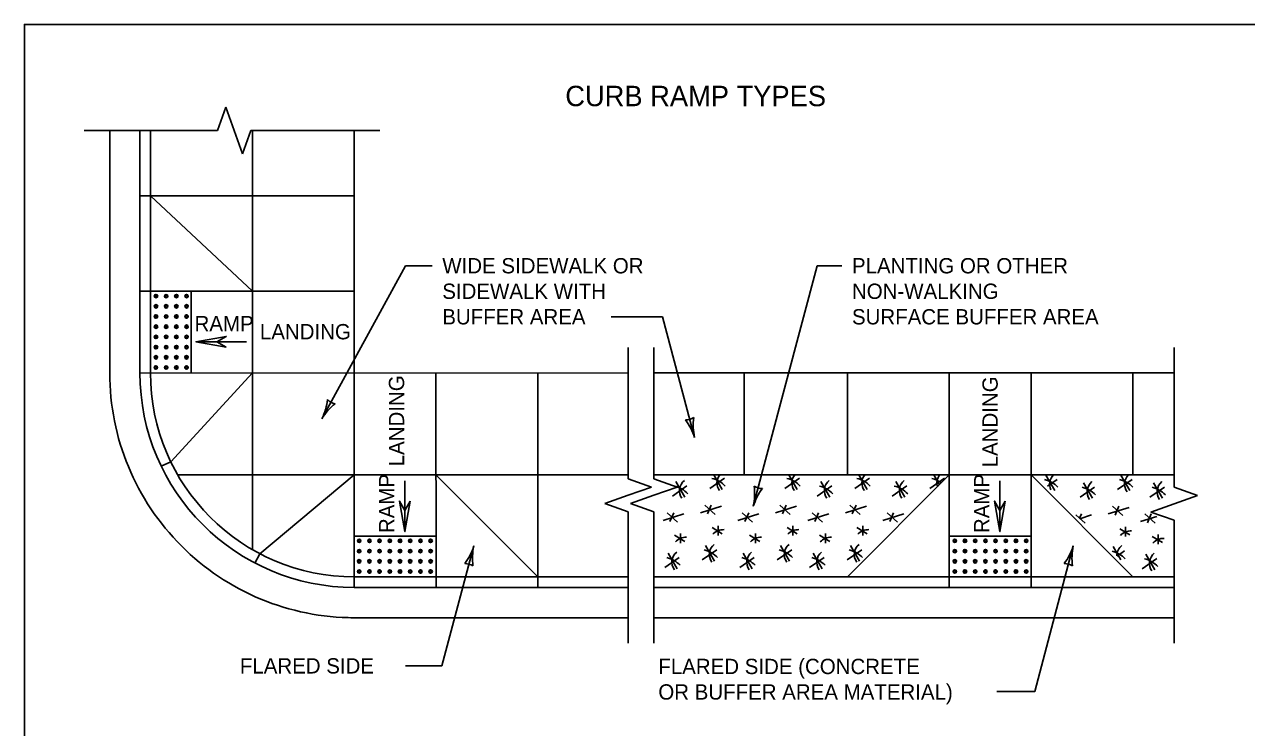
# Model space of a CAD drawing. Extents: x 49991.4 to 50021, y 49987.6 to 50011.4.
# Drawn here: x 50009.737 to 50014.53, y 50005.41 to 50008.165 of the extents above; entities that cross this region are included whole.
import ezdxf

# ---------------------------------------------------------------- set-up
doc = ezdxf.new("R2010")
doc.units = 0
for name, color, linetype in [('Level 1', 7, 'Continuous'), ('Level 2', 7, 'Continuous'), ('Level 3', 7, 'Continuous'), ('Level 6', 7, 'Continuous')]:
    doc.layers.add(name, color=color, linetype=linetype)

msp = doc.modelspace()

# ---------------------------------------------------------------- linework, layer by layer
at = {"layer": 'Level 1'}
for p, q in [((50010.072, 50006.7991), (50010.072, 50007.7489)), ((50010.1902, 50007.7489), (50010.1902, 50006.7991)), ((50010.2316, 50006.7991), (50010.2316, 50007.7489)), ((50010.6315, 50007.749), (50010.6315, 50006.1068)), ((50011.0308, 50007.749), (50011.0308, 50005.9583)), ((50011.0304, 50007.4931), (50010.1902, 50007.493)), ((50010.2314, 50007.493), (50010.6315, 50007.1196)), ((50011.0308, 50007.1196), (50010.1902, 50007.1195)), ((50010.3916, 50006.799), (50010.3917, 50007.1195)), ((50012.1053, 50006.7984), (50010.1902, 50006.7991)), ((50010.3113, 50006.4512), (50010.6315, 50006.799)), ((50011.3512, 50006.7988), (50011.3513, 50005.9583)), ((50011.7505, 50006.7989), (50011.7504, 50005.9584)), ((50012.2049, 50006.799), (50014.2452, 50006.7989)), ((50012.5597, 50006.7987), (50012.5598, 50006.3996)), ((50012.9648, 50006.7989), (50012.9647, 50006.3996)), ((50013.3641, 50006.799), (50013.3641, 50005.9585)), ((50013.6845, 50006.799), (50013.6846, 50005.9585)), ((50014.0838, 50006.7991), (50014.0838, 50006.3995)), ((50010.274, 50006.4332), (50010.3113, 50006.4512)), ((50012.1053, 50006.3995), (50010.3387, 50006.3995)), ((50010.6605, 50006.0909), (50011.0309, 50006.3997)), ((50011.3512, 50006.3996), (50011.7504, 50005.9998)), ((50012.2049, 50006.3996), (50014.2452, 50006.3995)), ((50012.205, 50006.3844), (50012.208, 50006.3865)), ((50012.2915, 50006.3732), (50012.3267, 50006.3122)), ((50012.4252, 50006.3469), (50012.4823, 50006.3865)), ((50012.4407, 50006.3996), (50012.4739, 50006.3422)), ((50012.7192, 50006.3469), (50012.7763, 50006.3865)), ((50012.7347, 50006.3996), (50012.7679, 50006.3422)), ((50012.8598, 50006.3732), (50012.895, 50006.3122)), ((50012.9645, 50005.9997), (50013.3641, 50006.3996)), ((50012.9935, 50006.3469), (50013.0506, 50006.3865)), ((50013.009, 50006.3996), (50013.0422, 50006.3422)), ((50013.1538, 50006.3732), (50013.189, 50006.3122)), ((50013.2875, 50006.3469), (50013.3446, 50006.3865)), ((50013.303, 50006.3996), (50013.3254, 50006.3609)), ((50013.6845, 50006.3997), (50014.0837, 50005.9997)), ((50013.743, 50006.3989), (50013.7783, 50006.3379)), ((50013.7485, 50006.3556), (50013.7867, 50006.3821)), ((50013.8899, 50006.3689), (50013.9251, 50006.3079)), ((50014.0236, 50006.3425), (50014.0807, 50006.3821)), ((50014.037, 50006.3989), (50014.0723, 50006.3379)), ((50014.1642, 50006.3689), (50014.1995, 50006.3079)), ((50012.2781, 50006.3169), (50012.3351, 50006.3565)), ((50012.8464, 50006.3169), (50012.9035, 50006.3565)), ((50013.1404, 50006.3169), (50013.1975, 50006.3565)), ((50013.8765, 50006.3125), (50013.9336, 50006.3521)), ((50014.1508, 50006.3125), (50014.2079, 50006.3521)), ((50012.1315, 50006.2808), (50012.1309, 50006.2814)), ((50012.3885, 50006.2509), (50012.4707, 50006.2769)), ((50012.4456, 50006.2448), (50012.4053, 50006.2814)), ((50012.4154, 50006.2464), (50012.4305, 50006.2814)), ((50012.6825, 50006.2509), (50012.7647, 50006.2769)), ((50012.7396, 50006.2448), (50012.6993, 50006.2814)), ((50012.7094, 50006.2464), (50012.7245, 50006.2814)), ((50012.9569, 50006.2509), (50013.039, 50006.2769)), ((50013.0139, 50006.2448), (50012.9736, 50006.2814)), ((50012.9837, 50006.2464), (50012.9988, 50006.2814)), ((50013.987, 50006.2465), (50014.0691, 50006.2725)), ((50014.044, 50006.2405), (50014.0037, 50006.277)), ((50014.0138, 50006.242), (50014.0289, 50006.277)), ((50012.2414, 50006.2209), (50012.3236, 50006.2469)), ((50012.2985, 50006.2148), (50012.2581, 50006.2514)), ((50012.2683, 50006.2164), (50012.2834, 50006.2514)), ((50012.5354, 50006.2209), (50012.6176, 50006.2469)), ((50012.5925, 50006.2148), (50012.5521, 50006.2514)), ((50012.5623, 50006.2164), (50012.5774, 50006.2514)), ((50012.8097, 50006.2209), (50012.8919, 50006.2469)), ((50012.8668, 50006.2148), (50012.8264, 50006.2514)), ((50012.8366, 50006.2164), (50012.8517, 50006.2514)), ((50013.1037, 50006.2209), (50013.1859, 50006.2469)), ((50013.1608, 50006.2148), (50013.1204, 50006.2514)), ((50013.1306, 50006.2164), (50013.1457, 50006.2514)), ((50013.8969, 50006.2105), (50013.8603, 50006.2436)), ((50013.8743, 50006.2296), (50013.8818, 50006.247)), ((50013.8759, 50006.228), (50013.922, 50006.2425)), ((50014.1142, 50006.2165), (50014.1773, 50006.2365)), ((50014.1712, 50006.2105), (50014.1309, 50006.247)), ((50014.141, 50006.212), (50014.1561, 50006.247)), ((50012.4336, 50006.1929), (50012.4739, 50006.1685)), ((50012.457, 50006.1625), (50012.457, 50006.2006)), ((50012.7276, 50006.1929), (50012.7679, 50006.1685)), ((50012.751, 50006.1625), (50012.751, 50006.2006)), ((50013.002, 50006.1929), (50013.0422, 50006.1685)), ((50013.0254, 50006.1625), (50013.0254, 50006.2006)), ((50014.0321, 50006.1886), (50014.0723, 50006.1642)), ((50014.0555, 50006.1581), (50014.0555, 50006.1962)), ((50011.3513, 50006.1597), (50011.0308, 50006.1597)), ((50012.2865, 50006.1629), (50012.3267, 50006.1385)), ((50012.3099, 50006.1325), (50012.3099, 50006.1706)), ((50012.5805, 50006.1629), (50012.6207, 50006.1385)), ((50012.6039, 50006.1325), (50012.6039, 50006.1706)), ((50012.8548, 50006.1629), (50012.895, 50006.1385)), ((50012.8782, 50006.1325), (50012.8782, 50006.1706)), ((50013.6846, 50006.1597), (50013.3641, 50006.1597)), ((50014.1592, 50006.1586), (50014.1995, 50006.1342)), ((50014.1826, 50006.1281), (50014.1826, 50006.1662)), ((50010.6413, 50006.0542), (50010.6605, 50006.0909)), ((50012.2615, 50006.0927), (50012.2967, 50006.0318)), ((50012.3952, 50006.0664), (50012.4523, 50006.106)), ((50012.4086, 50006.1227), (50012.4439, 50006.0618)), ((50012.5555, 50006.0927), (50012.5907, 50006.0318)), ((50012.6892, 50006.0664), (50012.7463, 50006.106)), ((50012.7026, 50006.1227), (50012.7379, 50006.0618)), ((50012.8298, 50006.0927), (50012.865, 50006.0318)), ((50012.9635, 50006.0664), (50013.0206, 50006.106)), ((50012.9769, 50006.1227), (50013.0122, 50006.0618)), ((50014.007, 50006.1184), (50014.037, 50006.0666)), ((50014.0219, 50006.0817), (50014.0507, 50006.1016)), ((50014.1342, 50006.0884), (50014.1695, 50006.0274)), ((50012.2481, 50006.0364), (50012.3051, 50006.076)), ((50012.5421, 50006.0364), (50012.5991, 50006.076)), ((50012.8164, 50006.0364), (50012.8735, 50006.076)), ((50014.1208, 50006.032), (50014.1779, 50006.0716)), ((50012.1052, 50005.9997), (50011.0308, 50005.9997)), ((50014.2452, 50005.9997), (50012.205, 50005.9997)), ((50011.0308, 50005.9583), (50012.1052, 50005.9583)), ((50012.205, 50005.9583), (50014.2452, 50005.9583)), ((50011.017, 50005.8401), (50012.1052, 50005.8401)), ((50012.205, 50005.8401), (50014.2452, 50005.84))]:
    msp.add_line(p, q, dxfattribs=at)
msp.add_lwpolyline([(50020.9378, 50008.1646), (50009.7374, 50008.1646), (50009.7374, 49999.8856), (50020.9378, 49999.8856)], close=True, dxfattribs=at)
msp.add_lwpolyline([(50020.9378, 50008.1646), (50009.7374, 50008.1646), (50009.7374, 49999.8856), (50020.9378, 49999.8856)], close=True, dxfattribs=at)
for centre, radius in [((50010.2531, 50007.1003), 0.00675), ((50010.2531, 50007.1003), 0.00375), ((50010.2931, 50007.1003), 0.00675), ((50010.2931, 50007.1003), 0.00375), ((50010.3331, 50007.1003), 0.00675), ((50010.3331, 50007.1003), 0.00375), ((50010.3731, 50007.1003), 0.00675), ((50010.3731, 50007.1003), 0.00375), ((50010.2531, 50007.0603), 0.00675), ((50010.2531, 50007.0603), 0.00375), ((50010.2931, 50007.0603), 0.00675), ((50010.2931, 50007.0603), 0.00375), ((50010.3331, 50007.0603), 0.00675), ((50010.3331, 50007.0603), 0.00375), ((50010.3731, 50007.0603), 0.00675), ((50010.3731, 50007.0603), 0.00375), ((50010.2531, 50007.0203), 0.00675), ((50010.2531, 50007.0203), 0.00375), ((50010.2931, 50007.0203), 0.00675), ((50010.2931, 50007.0203), 0.00375), ((50010.3331, 50007.0203), 0.00675), ((50010.3331, 50007.0203), 0.00375), ((50010.3731, 50007.0203), 0.00675), ((50010.3731, 50007.0203), 0.00375), ((50010.2531, 50006.9803), 0.00675), ((50010.2531, 50006.9403), 0.00675), ((50010.2531, 50006.9803), 0.00375), ((50010.2531, 50006.9403), 0.00375), ((50010.2931, 50006.9803), 0.00675), ((50010.2931, 50006.9403), 0.00675), ((50010.2931, 50006.9803), 0.00375), ((50010.2931, 50006.9403), 0.00375), ((50010.3331, 50006.9803), 0.00675), ((50010.3331, 50006.9403), 0.00675), ((50010.3331, 50006.9803), 0.00375), ((50010.3331, 50006.9403), 0.00375), ((50010.3731, 50006.9803), 0.00675), ((50010.3731, 50006.9403), 0.00675), ((50010.3731, 50006.9803), 0.00375), ((50010.3731, 50006.9403), 0.00375), ((50010.2531, 50006.9003), 0.00675), ((50010.2531, 50006.9003), 0.00375), ((50010.2931, 50006.9003), 0.00675), ((50010.2931, 50006.9003), 0.00375), ((50010.3331, 50006.9003), 0.00675), ((50010.3331, 50006.9003), 0.00375), ((50010.3731, 50006.9003), 0.00675), ((50010.3731, 50006.9003), 0.00375), ((50010.253, 50006.8603), 0.00675), ((50010.253, 50006.8603), 0.00375), ((50010.293, 50006.8603), 0.00675), ((50010.293, 50006.8603), 0.00375), ((50010.333, 50006.8603), 0.00675), ((50010.333, 50006.8603), 0.00375), ((50010.373, 50006.8603), 0.00675), ((50010.373, 50006.8603), 0.00375), ((50010.253, 50006.8203), 0.00675), ((50010.253, 50006.8203), 0.00375), ((50010.293, 50006.8203), 0.00675), ((50010.293, 50006.8203), 0.00375), ((50010.333, 50006.8203), 0.00675), ((50010.333, 50006.8203), 0.00375), ((50010.373, 50006.8203), 0.00675), ((50010.373, 50006.8203), 0.00375), ((50011.0501, 50006.1411), 0.00675), ((50011.0501, 50006.1411), 0.00375), ((50011.0901, 50006.1411), 0.00675), ((50011.0901, 50006.1411), 0.00375), ((50011.1301, 50006.1411), 0.00675), ((50011.1301, 50006.1411), 0.00375), ((50011.1701, 50006.1411), 0.00675), ((50011.1701, 50006.1411), 0.00375), ((50011.2101, 50006.1411), 0.00675), ((50011.2101, 50006.1411), 0.00375), ((50011.2501, 50006.1411), 0.00675), ((50011.2501, 50006.1411), 0.00375), ((50011.2901, 50006.1411), 0.00675), ((50011.2901, 50006.1411), 0.00375), ((50011.3301, 50006.1411), 0.00675), ((50011.3301, 50006.1411), 0.00375), ((50013.3855, 50006.1411), 0.00675), ((50013.3855, 50006.1411), 0.00375), ((50013.4255, 50006.1411), 0.00675), ((50013.4255, 50006.1411), 0.00375), ((50013.4655, 50006.1411), 0.00675), ((50013.4655, 50006.1411), 0.00375), ((50013.5055, 50006.1411), 0.00675), ((50013.5055, 50006.1411), 0.00375), ((50013.5455, 50006.1411), 0.00675), ((50013.5455, 50006.1411), 0.00375), ((50013.5855, 50006.1411), 0.00675), ((50013.5855, 50006.1411), 0.00375), ((50013.6255, 50006.1411), 0.00675), ((50013.6255, 50006.1411), 0.00375), ((50013.6655, 50006.1411), 0.00675), ((50013.6655, 50006.1411), 0.00375), ((50011.0501, 50006.1011), 0.00675), ((50011.0501, 50006.1011), 0.00375), ((50011.0901, 50006.1011), 0.00675), ((50011.0901, 50006.1011), 0.00375), ((50011.1301, 50006.1011), 0.00675), ((50011.1301, 50006.1011), 0.00375), ((50011.1701, 50006.1011), 0.00675), ((50011.1701, 50006.1011), 0.00375), ((50011.2101, 50006.1011), 0.00675), ((50011.2101, 50006.1011), 0.00375), ((50011.2501, 50006.1011), 0.00675), ((50011.2501, 50006.1011), 0.00375), ((50011.2901, 50006.1011), 0.00675), ((50011.2901, 50006.1011), 0.00375), ((50011.3301, 50006.1011), 0.00675), ((50011.3301, 50006.1011), 0.00375), ((50013.3855, 50006.1011), 0.00675), ((50013.3855, 50006.1011), 0.00375), ((50013.4255, 50006.1011), 0.00675), ((50013.4255, 50006.1011), 0.00375), ((50013.4655, 50006.1011), 0.00675), ((50013.4655, 50006.1011), 0.00375), ((50013.5055, 50006.1011), 0.00675), ((50013.5055, 50006.1011), 0.00375), ((50013.5455, 50006.1011), 0.00675), ((50013.5455, 50006.1011), 0.00375), ((50013.5855, 50006.1011), 0.00675), ((50013.5855, 50006.1011), 0.00375), ((50013.6255, 50006.1011), 0.00675), ((50013.6255, 50006.1011), 0.00375), ((50013.6655, 50006.1011), 0.00675), ((50013.6655, 50006.1011), 0.00375), ((50011.0501, 50006.0611), 0.00675), ((50011.0501, 50006.0611), 0.00375), ((50011.0901, 50006.0611), 0.00675), ((50011.0901, 50006.0611), 0.00375), ((50011.1301, 50006.0611), 0.00675), ((50011.1301, 50006.0611), 0.00375), ((50011.1701, 50006.0611), 0.00675), ((50011.1701, 50006.0611), 0.00375), ((50011.2101, 50006.0611), 0.00675), ((50011.2101, 50006.0611), 0.00375), ((50011.2501, 50006.0611), 0.00675), ((50011.2501, 50006.0611), 0.00375), ((50011.2901, 50006.0611), 0.00675), ((50011.2901, 50006.0611), 0.00375), ((50011.3301, 50006.0611), 0.00675), ((50011.3301, 50006.0611), 0.00375), ((50013.3855, 50006.0611), 0.00675), ((50013.3855, 50006.0611), 0.00375), ((50013.4255, 50006.0611), 0.00675), ((50013.4255, 50006.0611), 0.00375), ((50013.4655, 50006.0611), 0.00675), ((50013.4655, 50006.0611), 0.00375), ((50013.5055, 50006.0611), 0.00675), ((50013.5055, 50006.0611), 0.00375), ((50013.5455, 50006.0611), 0.00675), ((50013.5455, 50006.0611), 0.00375), ((50013.5855, 50006.0611), 0.00675), ((50013.5855, 50006.0611), 0.00375), ((50013.6255, 50006.0611), 0.00675), ((50013.6255, 50006.0611), 0.00375), ((50013.6655, 50006.0611), 0.00675), ((50013.6655, 50006.0611), 0.00375), ((50011.0501, 50006.0211), 0.00675), ((50011.0501, 50006.0211), 0.00375), ((50011.0901, 50006.0211), 0.00675), ((50011.0901, 50006.0211), 0.00375), ((50011.1301, 50006.0211), 0.00675), ((50011.1301, 50006.0211), 0.00375), ((50011.1701, 50006.0211), 0.00675), ((50011.1701, 50006.0211), 0.00375), ((50011.2101, 50006.0211), 0.00675), ((50011.2101, 50006.0211), 0.00375), ((50011.2501, 50006.0211), 0.00675), ((50011.2501, 50006.0211), 0.00375), ((50011.2901, 50006.0211), 0.00675), ((50011.2901, 50006.0211), 0.00375), ((50011.3301, 50006.0211), 0.00675), ((50011.3301, 50006.0211), 0.00375), ((50013.3855, 50006.0211), 0.00675), ((50013.3855, 50006.0211), 0.00375), ((50013.4255, 50006.0211), 0.00675), ((50013.4255, 50006.0211), 0.00375), ((50013.4655, 50006.0211), 0.00675), ((50013.4655, 50006.0211), 0.00375), ((50013.5055, 50006.0211), 0.00675), ((50013.5055, 50006.0211), 0.00375), ((50013.5455, 50006.0211), 0.00675), ((50013.5455, 50006.0211), 0.00375), ((50013.5855, 50006.0211), 0.00675), ((50013.5855, 50006.0211), 0.00375), ((50013.6255, 50006.0211), 0.00675), ((50013.6255, 50006.0211), 0.00375), ((50013.6655, 50006.0211), 0.00675), ((50013.6655, 50006.0211), 0.00375)]:
    msp.add_circle(centre, radius, dxfattribs=at)
for centre, radius, start in [((50011.0308, 50006.7989), 0.9588, 179.9835), ((50011.0308, 50006.7992), 0.8406, 180), ((50011.0308, 50006.7992), 0.7992, 180)]:
    msp.add_arc(centre, radius, start, 270, dxfattribs=at)
for centre, major_axis, start_param, end_param in [((50012.3648, 50006.3382), (-0.0591, 0), 5.450961, 6.875887), ((50012.4046, 50006.2919), (0.1074, 0), 0.715682, 1.301104), ((50012.5119, 50006.3682), (-0.0591, 0), 5.658518, 6.875887), ((50012.6986, 50006.2919), (0.1074, 0), 0.715682, 1.301104), ((50012.8059, 50006.3682), (-0.0591, 0), 5.658734, 6.875887), ((50012.9331, 50006.3382), (-0.0591, 0), 5.450961, 6.875887), ((50012.9729, 50006.2919), (0.1074, 0), 0.715682, 1.301104), ((50013.0803, 50006.3682), (-0.0591, 0), 5.658934, 6.875887), ((50013.2271, 50006.3382), (-0.0591, 0), 5.450961, 6.875887), ((50013.2669, 50006.2919), (0.1074, 0), 0.904787, 1.301104), ((50013.3743, 50006.3682), (-0.0591, 0), 5.65915, 6.569161), ((50013.709, 50006.2876), (0.1074, 0), 0.715682, 1.301104), ((50013.8164, 50006.3638), (-0.0591, 0), 5.55586, 6.714637), ((50013.9632, 50006.3338), (-0.0591, 0), 5.450961, 6.875887), ((50014.003, 50006.2876), (0.1074, 0), 0.715682, 1.301104), ((50014.1104, 50006.3638), (-0.0591, 0), 5.556094, 6.875887), ((50014.2376, 50006.3338), (-0.0591, 0), 5.450961, 6.875887), ((50012.2574, 50006.2619), (0.1074, 0), 0.715682, 1.301104), ((50012.8258, 50006.2619), (0.1074, 0), 0.715682, 1.301104), ((50013.1198, 50006.2619), (0.1074, 0), 0.715682, 1.301104), ((50013.8559, 50006.2576), (0.1074, 0), 0.715682, 1.301104), ((50014.1302, 50006.2576), (0.1074, 0), 0.715682, 1.301104), ((50012.2063, 50006.1332), (-0.0573, 0), 4.712389, 4.735904), ((50012.4806, 50006.1332), (-0.0573, 0), 4.712389, 5.577205), ((50012.7746, 50006.1332), (-0.0573, 0), 4.712389, 5.577205), ((50013.0489, 50006.1332), (-0.0573, 0), 4.712389, 5.577205), ((50014.079, 50006.1289), (-0.0573, 0), 4.712389, 5.577205), ((50012.3335, 50006.1032), (-0.0573, 0), 4.712389, 5.577205), ((50012.4819, 50006.0877), (-0.0591, 0), 5.450961, 6.875887), ((50012.6275, 50006.1032), (-0.0573, 0), 4.712389, 5.577205), ((50012.7759, 50006.0877), (-0.0591, 0), 5.450961, 6.875887), ((50012.9018, 50006.1032), (-0.0573, 0), 4.712389, 5.577205), ((50013.0503, 50006.0877), (-0.0591, 0), 5.450961, 6.875887), ((50014.2062, 50006.0989), (-0.0573, 0), 4.712389, 5.577205), ((50012.3348, 50006.0577), (-0.0591, 0), 5.450961, 6.875887), ((50012.3746, 50006.0114), (0.1074, 0), 0.715682, 1.301104), ((50012.6288, 50006.0577), (-0.0591, 0), 5.450961, 6.875887), ((50012.6686, 50006.0114), (0.1074, 0), 0.715682, 1.301104), ((50012.9031, 50006.0577), (-0.0591, 0), 5.450961, 6.875887), ((50012.9429, 50006.0114), (0.1074, 0), 0.715682, 1.301104), ((50013.973, 50006.0071), (0.1074, 0), 0.715682, 1.290796), ((50014.0804, 50006.0834), (-0.0591, 0), 5.450961, 6.303548), ((50014.2076, 50006.0534), (-0.0591, 0), 5.450961, 6.875887), ((50012.2274, 50005.9814), (0.1074, 0), 0.715682, 1.301104), ((50012.5214, 50005.9814), (0.1074, 0), 0.715682, 1.301104), ((50012.7958, 50005.9814), (0.1074, 0), 0.715682, 1.301104), ((50014.1002, 50005.9771), (0.1074, 0), 0.715682, 1.301104)]:
    msp.add_ellipse(centre, major_axis=major_axis, ratio=0.909091, start_param=start_param, end_param=end_param, dxfattribs=at)
at = {"layer": 'Level 3'}
for p, q in [((50010.9041, 50006.6198), (50011.2316, 50007.2192)), ((50011.2316, 50007.2192), (50011.3359, 50007.2192)), ((50012.5954, 50006.2773), (50012.8455, 50007.2192)), ((50012.8455, 50007.2192), (50012.9423, 50007.2192)), ((50012.2394, 50007.0192), (50012.038, 50007.0192)), ((50012.365, 50006.5464), (50012.2394, 50007.0192)), ((50010.4095, 50006.9211), (50010.6082, 50006.921)), ((50011.2293, 50006.1775), (50011.2293, 50006.3762)), ((50013.5626, 50006.1775), (50013.5626, 50006.3762)), ((50011.4994, 50006.1211), (50011.3747, 50005.6514)), ((50013.8502, 50006.1211), (50013.699, 50005.5514)), ((50011.2316, 50005.6514), (50011.3747, 50005.6514)), ((50013.699, 50005.5514), (50013.5505, 50005.5514))]:
    msp.add_line(p, q, dxfattribs=at)
for points in [[(50010.5286, 50006.9002), (50010.4095, 50006.9211), (50010.5286, 50006.9423), (50010.4923, 50006.9212)], [(50011.2501, 50006.2967), (50011.2293, 50006.1775), (50011.208, 50006.2967), (50011.2291, 50006.2603)], [(50013.5834, 50006.2967), (50013.5626, 50006.1775), (50013.5413, 50006.2967), (50013.5624, 50006.2603)]]:
    msp.add_lwpolyline(points, close=True, dxfattribs=at)
for centre, radius, start, end in [((50010.6944, 50006.7213), 0.233, 334.1831, 353.4329), ((50011.0947, 50006.5053), 0.2223, 128.8118, 148.9953), ((50010.9656, 50006.7323), 0.0548, 223.4946, 259.2169), ((50012.3321, 50006.6703), 0.0548, 267.0048, 302.7271), ((50012.1526, 50006.4805), 0.2223, 17.2264, 37.4099), ((50012.5928, 50006.595), 0.233, 172.7888, 192.0386), ((50012.3676, 50006.3259), 0.233, 347.9614, 7.2112), ((50012.8078, 50006.2115), 0.2223, 142.5901, 162.7736), ((50012.6283, 50006.4013), 0.0548, 237.2729, 272.9952), ((50011.2871, 50006.1869), 0.2223, 322.5901, 342.7736), ((50011.7273, 50006.0725), 0.233, 167.9614, 187.2112), ((50013.6379, 50006.1869), 0.2223, 322.5901, 342.7736), ((50014.0781, 50006.0725), 0.233, 167.9614, 187.2112), ((50011.4665, 50005.9972), 0.0548, 57.2729, 92.9952), ((50013.8173, 50005.9972), 0.0548, 57.2729, 92.9952)]:
    msp.add_arc(centre, radius, start, end, dxfattribs=at)
at = {"layer": 'Level 6'}
for p, q in [((50010.495, 50007.7489), (50010.5274, 50007.8403)), ((50010.5274, 50007.8403), (50010.5598, 50007.7489)), ((50009.972, 50007.7489), (50010.495, 50007.7489)), ((50010.5598, 50007.7489), (50010.5922, 50007.6575)), ((50010.5922, 50007.6575), (50010.6246, 50007.7489)), ((50010.6246, 50007.7489), (50011.1308, 50007.7489)), ((50012.1053, 50006.8984), (50012.1053, 50006.3844)), ((50012.2049, 50006.899), (50012.2049, 50006.3844)), ((50014.2452, 50006.8989), (50014.2452, 50006.3512)), ((50012.1967, 50006.352), (50012.1053, 50006.3844)), ((50012.2963, 50006.352), (50012.2049, 50006.3844)), ((50012.1053, 50006.3196), (50012.0139, 50006.2872)), ((50012.1967, 50006.352), (50012.1053, 50006.3196)), ((50012.2049, 50006.3196), (50012.1135, 50006.2872)), ((50012.2963, 50006.352), (50012.2049, 50006.3196)), ((50014.2452, 50006.3512), (50014.3366, 50006.3188)), ((50014.3366, 50006.3188), (50014.2452, 50006.2864)), ((50012.1053, 50006.2548), (50012.0139, 50006.2872)), ((50012.2049, 50006.2548), (50012.1135, 50006.2872)), ((50014.2452, 50006.2864), (50014.1538, 50006.254)), ((50012.1053, 50006.2548), (50012.1053, 50005.7401)), ((50012.2049, 50006.2548), (50012.2049, 50005.7401)), ((50014.1538, 50006.254), (50014.2452, 50006.2216)), ((50014.2452, 50006.2216), (50014.2452, 50005.74))]:
    msp.add_line(p, q, dxfattribs=at)

# ---------------------------------------------------------------- texts
at = {"layer": 'Level 2'}
for s, height, p in [('CURB RAMP TYPES', 0.08, (50011.8582, 50007.8443)), ('WIDE SIDEWALK OR', 0.06, (50011.3759, 50007.1892)), ('PLANTING OR OTHER', 0.06, (50012.9823, 50007.1892)), ('SIDEWALK WITH', 0.06, (50011.3759, 50007.0892)), ('NON-WALKING', 0.06, (50012.9823, 50007.0892)), ('BUFFER AREA', 0.06, (50011.3759, 50006.9892)), ('SURFACE BUFFER AREA', 0.06, (50012.9823, 50006.9892)), ('FLARED SIDE', 0.06, (50010.5821, 50005.6214)), ('FLARED SIDE (CONCRETE', 0.06, (50012.223, 50005.6191)), ('OR BUFFER AREA MATERIAL)', 0.06, (50012.223, 50005.5191))]:
    msp.add_text(s, height=height, dxfattribs=at).set_placement(p)
for s, rotation, p in [('RAMP', 359.9804, (50010.4045, 50006.9625)), ('LANDING', 359.9804, (50010.6607, 50006.9309)), ('LANDING', 90, (50011.2264, 50006.4332)), ('LANDING', 90, (50013.5538, 50006.4292)), ('RAMP', 90, (50011.1879, 50006.1717)), ('RAMP', 90, (50013.5212, 50006.1717))]:
    msp.add_text(s, height=0.06, rotation=rotation, dxfattribs=at).set_placement(p)

doc.saveas('drawing.dxf')
